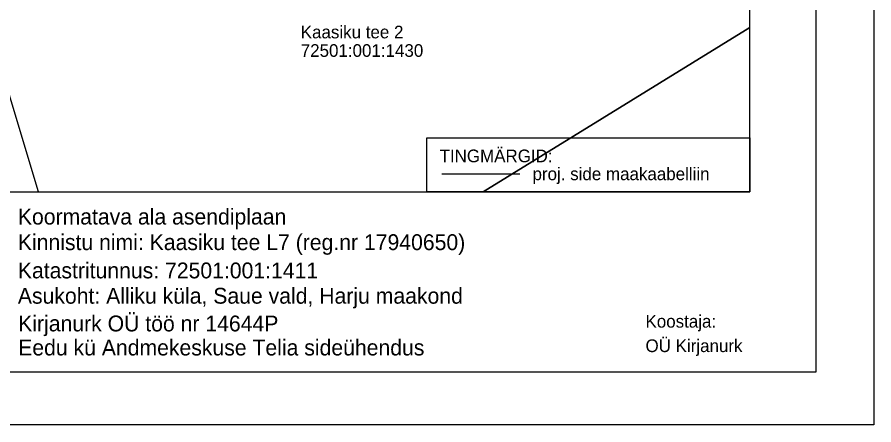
# Model space of a CAD drawing. Extents: x 532656 to 533339, y 6581345 to 6581629.
# Drawn here: x 533136.1 to 533338.9, y 6581366.5 to 6581463.1 of the extents above; entities that cross this region are included whole.
import ezdxf

# ---------------------------------------------------------------- set-up
doc = ezdxf.new("R2010")
doc.units = 0
doc.layers.add('PIIR', color=7, linetype='Continuous')
doc.layers.add('VORMISTUS', color=7, linetype='Continuous')

msp = doc.modelspace()

# ---------------------------------------------------------------- linework, layer by layer
at = {"layer": 'PIIR'}
for p, q in [((533309.59, 6581460.61), (533246.47, 6581421.68)), ((533246.48, 6581421.68), (533309.59, 6581460.6))]:
    msp.add_line(p, q, dxfattribs=at)
for points in [[(533141.13, 6581421.68), (533127.07, 6581468.59), (533267.77, 6581502.5), (533292.38, 6581484.15), (533309.59, 6581464.94)], [(533141.13, 6581421.68), (533127.07, 6581468.59), (533123.26, 6581468.15), (533035.33, 6581479.69), (533032.98, 6581458.23), (533019.26, 6581430.2), (532997.7, 6581433.84)]]:
    msp.add_lwpolyline(points, dxfattribs=at)
at = {"layer": 'VORMISTUS'}
for p, q in [((533236.66, 6581425.96), (533255.13, 6581425.96)), ((533325.2, 6581379.01), (533325.2, 6581379.01))]:
    msp.add_line(p, q, dxfattribs=at)
for points in [[(532967.7, 6581629.01), (533338.95, 6581629.01), (533338.95, 6581366.51), (532967.7, 6581366.51)], [(532981.45, 6581379.01), (532981.45, 6581616.51), (533325.2, 6581616.51), (533325.2, 6581379.01)], [(532981.45, 6581616.51), (533325.2, 6581616.51), (533325.2, 6581379.01), (532981.45, 6581379.01)], [(533309.59, 6581421.68), (533309.59, 6581605.42), (532997.7, 6581605.42), (532997.7, 6581421.68)], [(533233.13, 6581421.68), (533233.13, 6581434.46), (533309.59, 6581434.46), (533309.59, 6581421.68)]]:
    msp.add_lwpolyline(points, close=True, dxfattribs=at)
for points in [[(533309.59, 6581421.68), (533309.59, 6581605.42)], [(532997.7, 6581421.68), (533309.59, 6581421.68)]]:
    msp.add_lwpolyline(points, dxfattribs=at)

# ---------------------------------------------------------------- texts
at = {"layer": 'PIIR'}
for s, p in [('Kaasiku tee 2', (533203.26, 6581458.05)), ('72501:001:1430', (533203.26, 6581453.67))]:
    msp.add_text(s, height=3, dxfattribs=at).set_placement(p)
at = {"layer": 'VORMISTUS'}
for s, height, p in [('TINGMÄRGID:', 3, (533236.13, 6581428.71)), ('proj. side maakaabelliin', 3, (533258.13, 6581424.46)), ('Koormatava ala asendiplaan', 3.75, (533136.28, 6581413.96)), ('Kinnistu nimi: Kaasiku tee L7 (reg.nr 17940650)', 3.75, (533136.28, 6581407.9)), ('Katastritunnus: 72501:001:1411', 3.75, (533136.28, 6581401.21)), ('Asukoht: Alliku küla, Saue vald, Harju maakond', 3.75, (533136.28, 6581395.21)), ('Koostaja:', 3, (533284.88, 6581389.54)), ('OÜ Kirjanurk', 3, (533284.88, 6581383.75))]:
    msp.add_text(s, height=height, dxfattribs=at).set_placement(p)
for s, p in [('Kirjanurk OÜ töö nr 14644P', (533136.36, 6581388.65)), ('Eedu kü Andmekeskuse Telia sideühendus', (533136.36, 6581382.95))]:
    msp.add_text(s, height=3.75, rotation=360, dxfattribs=at).set_placement(p)

doc.saveas('drawing.dxf')
